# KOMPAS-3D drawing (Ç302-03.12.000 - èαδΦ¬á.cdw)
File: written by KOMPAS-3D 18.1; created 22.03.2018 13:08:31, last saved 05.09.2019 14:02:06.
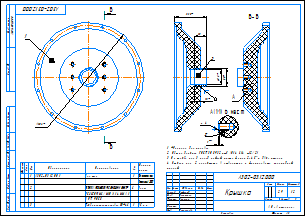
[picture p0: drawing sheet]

Sheet 1: A3, landscape

Document properties: Автор: Милов; Масса: 2.90403; Полное имя файла: ..\А302-00.00.000 - ASTRA-302 (МЭ200)\3Д ПВХ\А302-01.12.000 - Крышка.a3d

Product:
- Part/product: (unnamed)
  - Component: Труба полипропиленовая 50*4,6  | pos. 3  | Раздел спецификации: Детали; Примечание: 35 мм
  - Component: ВТУЛКА РЕЗЬБОВАЯ С ВНЕШН. И ВНУТР.  / РЕЗЬБОЙ M6/M10 X 14 ММ А1 / ART. 9058  | pos. 2  | Раздел спецификации: Детали; Примечание: Нерж.
  - Component: Крышка  | designation А302-03.12.001  | pos. 1  | Раздел спецификации: Детали; Примечание: Полипропилен / Стержень @2~300

Title block, sheet 1: Наименование: Крышка; designation: А302-03.12.000; Масса: 2,9; scale: 1:2; Количество листов документа: 1; organisation: АО «Астерион»; Форматы листов документа: A3; stored path: Z:\Мембранные насосы\Мембранный электропривод\А302-00.00.000 - ASTRA-302 (МЭ200)\Чертежи\А302-00.12.000 - Крышка.cdw; Разработал: Лифлянд; Проверил: Борисенко; Т. контр.: Лучихин; Утвердил: Григорьева

Views: Вид 1, Местный разрез 1, Вид:1, Выносной элемент 5, Разрез Б-Б, Выносной элемент А, Выносной элемент
Referenced files in D:\Мембранные насосы\Мембранный электропривод\А302-00.00.000 - ASTRA-302 (МЭ200)\3Д ПВХ\: А302-01.12.001 - Крышка.m3d, А302-01.12.000 - Крышка.a3d, А302-01.12.001 - Крышка.cdw, Втулка резьбовая М6 (шт.) Alutech.m3d
Referenced files in D:\1 ПКИ 3D\ПВХ фитинги, трубы\: Труба PVC-U 50 3,7.m3d
Referenced files in Z:\Мембранные насосы\Мембранный электропривод\А302-00.00.000 - ASTRA-302 (МЭ200)\3Д\: А302-00.12.000 - Крышка.a3d
Referenced files in D:\Мембранные насосы\Мембранный электропривод\А302-00.00.000 - ASTRA-302 (МЭ200)\3Д ПВХ\Отработка\: Труба ПВХ PN10 50х2,4.m3d
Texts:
  Труба ПВХ PN10 50х2,4
  @100~)2xA3
  ART. 9058 ВТУЛКА РЕЗЬБОВАЯ С ВНЕШН. И ВНУТР. РЕЗЬБОЙ M6 / M10 X 14 ММ А1-НЕРЖ
  - PP
  Труба полипропиленовая 50*4,6
  Полипропилен
  Стержень  300
  Полипропилен / Стержень @2~300
  ВТУЛКА РЕЗЬБОВАЯ С ВНЕШН. И ВНУТР.
  РЕЗЬБОЙ M6/M10 X 14 ММ А1
  ART. 9058
  ВТУЛКА РЕЗЬБОВАЯ С ВНЕШН. И ВНУТР.  / РЕЗЬБОЙ M6/M10 X 14 ММ А1 / ART. 9058
  Нерж.
Dimensions and other numbers on the sheet: 3; 35; 83,5; 50; 40,8; 18; 1; 2; 4; 130; 24; 25; 17; 14; 26; 27; 28; 12; 6; 35 мм; 1:2; 2,9

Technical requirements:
  *Размеры для справок.
  Общие допуски ГОСТ 30893.2-mK (H14, h14,  t2/2).
  На трубе поз. 3 перед пайкой снять фаски 2х45  с двух сторон.
  Втулки поз. 2 закрутить в отверстия и фиксировать эпоксидной
  смолой.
